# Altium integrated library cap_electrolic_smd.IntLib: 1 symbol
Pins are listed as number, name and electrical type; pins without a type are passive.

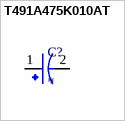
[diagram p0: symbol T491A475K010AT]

## T491A475K010AT
designator C?
4.7ÂµF Molded Tantalum Capacitors 10V 1206 (3216 Metric) 5Ohm; MP: T491A475K010AT; MF: KEMET
footprint CAPMP3216X180N
pins: 1, 2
